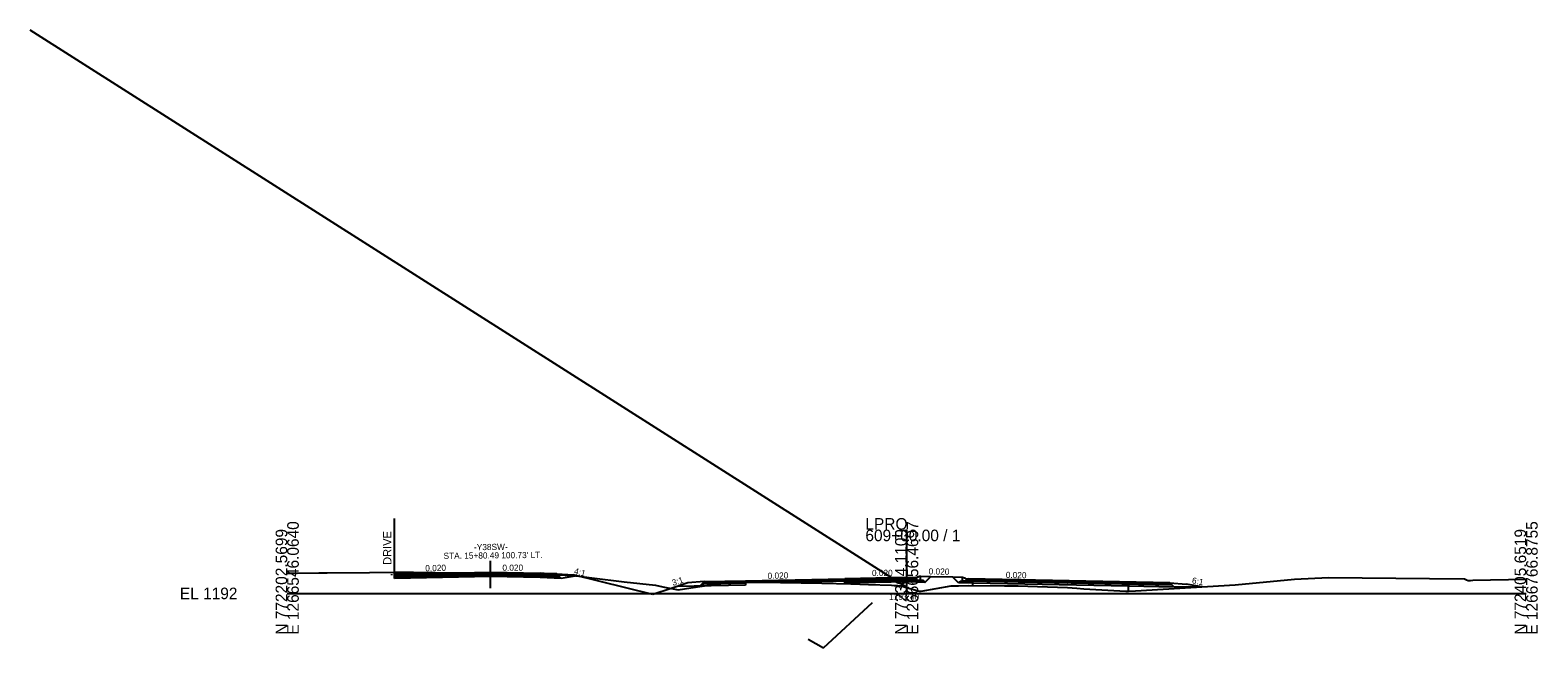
# Model space of a CAD drawing. Extents: x -3833 to 1267678, y -522 to 773248.
# Drawn here: x 1937.8 to 2302.8, y -13.2 to 136.5 of the extents above; entities that cross this region are included whole.
import ezdxf

# ---------------------------------------------------------------- set-up
doc = ezdxf.new("R2010")
doc.units = 0
for name, color, linetype in [('Exist Cross Section Cell', 7, 'Continuous'), ('Exist XS Center Line Elevation Label', 7, 'Continuous'), ('Exist XS Ground Line', 7, 'Continuous'), ('Prop CMT DNC', 7, 'Continuous'), ('Prop CMT Pvmt Course 1', 7, 'Continuous'), ('Prop CMT Pvmt Course 2', 7, 'Continuous'), ('Prop CMT Pvmt Course 3', 7, 'Continuous'), ('Prop CMT Pvmt Course 4', 7, 'Continuous'), ('Prop CMT Shld Paved Course 1', 7, 'Continuous'), ('Prop CMT Shld Paved Course 2', 7, 'Continuous'), ('Prop CMT Shld Paved Course 4', 7, 'Continuous'), ('Prop CMT Slope Fill', 7, 'Continuous'), ('Prop CMT Slope Grass', 7, 'Continuous'), ('Prop CMT Subgrade Earthwork', 7, 'Continuous'), ('Prop Conc Curb and Gutter', 7, 'Continuous'), ('Prop Conc Island Cover', 7, 'Continuous'), ('Prop Corridor Mesh Bottom', 7, 'Continuous'), ('Prop XS Ditch Slope Text', 7, 'Continuous'), ('Prop XS Finish Grade', 7, 'Continuous'), ('Prop XS SE Text', 7, 'Continuous'), ('Prop XS Shear Point Element', 7, 'Continuous'), ('Prop XS Shear Point Label', 7, 'Continuous'), ('Scratch_Level_1', 7, 'Continuous'), ('Scratch_Level_5', 7, 'Continuous'), ('Scratch_Level_9', 7, 'Continuous')]:
    doc.layers.add(name, color=color, linetype=linetype)

msp = doc.modelspace()

# ---------------------------------------------------------------- linework, layer by layer
at = {"layer": 'Exist Cross Section Cell'}
for p, q in [((2150, 0), (2150, 15.45)), ((2000, 0), (2150, 0)), ((2150, 0), (2300, 0))]:
    msp.add_line(p, q, dxfattribs=at)
at = {"layer": 'Exist XS Ground Line'}
for p, q in [((2000, 4.89), (2002.42, 4.91)), ((2002.42, 4.91), (2007.67, 4.95)), ((2007.67, 4.95), (2009.66, 4.95)), ((2009.66, 4.95), (2019.93, 5.08)), ((2019.93, 5.08), (2025.96, 5.13)), ((2025.96, 5.13), (2026.63, 5.13)), ((2026.63, 5.13), (2027.35, 5.13)), ((2027.35, 5.13), (2028.44, 5.15)), ((2028.44, 5.15), (2030.6, 5.14)), ((2030.6, 5.14), (2035.8, 5.1)), ((2035.8, 5.1), (2045.08, 5.01)), ((2045.08, 5.01), (2049.76, 4.95)), ((2049.76, 4.95), (2052.59, 4.91)), ((2052.59, 4.91), (2061.3, 4.64)), ((2061.3, 4.64), (2069.13, 4.35)), ((2069.13, 4.35), (2071.32, 4.12)), ((2071.32, 4.12), (2073.79, 3.81)), ((2073.79, 3.81), (2081.61, 2.84)), ((2243.9, 3.42), (2252.17, 3.82)), ((2252.17, 3.82), (2276.62, 3.62)), ((2081.61, 2.84), (2089.16, 1.96)), ((2089.16, 1.96), (2090.97, 1.59)), ((2090.97, 1.59), (2094.68, 0.88)), ((2094.68, 0.88), (2097.76, 1.34)), ((2097.76, 1.34), (2103.78, 2.22)), ((2103.78, 2.22), (2106.87, 2.62)), ((2106.87, 2.62), (2107.71, 2.73)), ((2107.71, 2.73), (2111.01, 2.75)), ((2111.01, 2.75), (2111.87, 2.75)), ((2111.87, 2.75), (2114.38, 2.72)), ((2114.38, 2.72), (2124.49, 2.58)), ((2124.49, 2.58), (2129.44, 2.47)), ((2129.44, 2.47), (2136.46, 2.31)), ((2136.46, 2.31), (2140.77, 2.16)), ((2140.77, 2.16), (2146.31, 1.97)), ((2146.31, 1.97), (2147.01, 1.94)), ((2147.01, 1.94), (2147.87, 1.9)), ((2147.87, 1.9), (2148.58, 1.81)), ((2148.58, 1.81), (2150.17, 1.36)), ((2150.17, 1.36), (2153.14, 0.51)), ((2153.14, 0.51), (2153.55, 0.58)), ((2153.55, 0.58), (2160.75, 1.85)), ((2160.75, 1.85), (2161.7, 1.86)), ((2161.7, 1.86), (2162.56, 1.87)), ((2162.56, 1.87), (2165.07, 1.92)), ((2165.07, 1.92), (2173.71, 1.86)), ((2173.71, 1.86), (2176.97, 1.83)), ((2176.97, 1.83), (2181.66, 1.67)), ((2181.66, 1.67), (2188.97, 1.42)), ((2188.97, 1.42), (2191.18, 1.26)), ((2191.18, 1.26), (2192.9, 1.13)), ((2192.9, 1.13), (2203.1, 0.57)), ((2203.1, 0.57), (2203.69, 0.54)), ((2203.69, 0.54), (2205.39, 0.63)), ((2205.39, 0.63), (2229.53, 2.1)), ((2229.53, 2.1), (2243.9, 3.42)), ((2276.62, 3.62), (2285.09, 3.55)), ((2285.09, 3.55), (2285.59, 3.32)), ((2285.59, 3.32), (2285.95, 3.13)), ((2285.95, 3.13), (2286.53, 3.15)), ((2286.53, 3.15), (2287.07, 3.17)), ((2287.07, 3.17), (2300, 3.46))]:
    msp.add_line(p, q, dxfattribs=at)
at = {"layer": 'Prop CMT Pvmt Course 1'}
for p, q in [((2026, 4.67), (2049.26, 5.14)), ((2049.26, 5.14), (2061.26, 4.9)), ((2061.26, 4.9), (2061.26, 4.9)), ((2061.26, 4.9), (2061.26, 4.65)), ((2061.26, 4.65), (2061.26, 4.65)), ((2061.26, 4.65), (2061.26, 4.65)), ((2111, 3.05), (2135, 3.53)), ((2111, 2.8), (2111, 3.05)), ((2111, 3.05), (2111, 3.05)), ((2135, 3.53), (2135, 3.53)), ((2135, 3.53), (2135, 3.53)), ((2135, 3.53), (2135, 3.28)), ((2135, 3.28), (2135, 3.28)), ((2213.69, 2.56), (2165, 3.53)), ((2165, 3.53), (2165, 3.53)), ((2165, 3.53), (2165, 3.53)), ((2165, 3.53), (2165, 3.28)), ((2165, 3.28), (2165, 3.28)), ((2189, 3.05), (2189, 3.05)), ((2189, 2.8), (2189, 2.8)), ((2189, 2.8), (2189, 2.8)), ((2189.06, 3.23), (2189.06, 3.23))]:
    msp.add_line(p, q, dxfattribs=at)
at = {"layer": 'Prop CMT Pvmt Course 2'}
for p, q in [((2026, 4.42), (2049.26, 4.89)), ((2049.26, 4.89), (2061.26, 4.65)), ((2061.26, 4.65), (2061.26, 4.65)), ((2061.26, 4.65), (2061.26, 4.31)), ((2061.26, 4.31), (2061.26, 4.31)), ((2061.26, 4.31), (2061.26, 4.31)), ((2150, 3.58), (2135, 3.28)), ((2135, 3.28), (2135, 3.28)), ((2135, 3.28), (2135, 2.95)), ((2135, 2.95), (2150, 3.25)), ((2135, 2.95), (2135, 2.95)), ((2151.84, 3.55), (2150, 3.58)), ((2150, 3.58), (2150, 3.58)), ((2150, 3.58), (2150, 3.58)), ((2150, 3.25), (2150, 3.25)), ((2150, 3.25), (2150, 3.25)), ((2150, 3.25), (2151.83, 3.21)), ((2165, 2.95), (2165, 3.28)), ((2165, 3.28), (2165, 3.28)), ((2165, 2.95), (2165, 2.95))]:
    msp.add_line(p, q, dxfattribs=at)
at = {"layer": 'Prop CMT Pvmt Course 3'}
msp.add_line((2154.42, 2.68), (2153.93, 3.17), dxfattribs=at)
at = {"layer": 'Prop CMT Pvmt Course 4'}
for p, q in [((2026, 4.09), (2049.26, 4.55)), ((2049.26, 4.55), (2061.26, 4.31)), ((2061.26, 4.31), (2061.26, 4.31)), ((2061.26, 4.31), (2061.26, 3.85)), ((2061.26, 3.85), (2061.26, 3.85)), ((2061.26, 3.85), (2061.26, 3.85)), ((2135, 2.34), (2135, 2.95)), ((2135, 2.95), (2135, 2.95)), ((2135, 2.95), (2135, 2.95)), ((2150, 3.25), (2150, 3.25)), ((2150, 3.25), (2150, 3.25)), ((2153.34, 3.19), (2153.93, 3.17)), ((2162.54, 2.54), (2162.99, 2.99)), ((2162.99, 2.99), (2163.49, 2.98)), ((2165, 2.95), (2165, 2.95)), ((2165, 2.95), (2165, 2.95)), ((2166, 2.47), (2166, 3.51)), ((2203.69, 1.72), (2166, 2.47)), ((2203.69, 2.76), (2203.69, 1.72))]:
    msp.add_line(p, q, dxfattribs=at)
at = {"layer": 'Prop CMT Shld Paved Course 1'}
for p, q in [((2062.24, 4.85), (2061.26, 4.9)), ((2061.26, 4.65), (2061.26, 4.65)), ((2061.26, 4.65), (2062.48, 4.59)), ((2065.26, 4.72), (2062.24, 4.85)), ((2062.48, 4.59), (2062.54, 4.59)), ((2062.54, 4.59), (2065.53, 4.45)), ((2065.53, 4.45), (2065.26, 4.72)), ((2150, 3.83), (2135, 3.53)), ((2151.85, 3.79), (2150, 3.83)), ((2150, 3.83), (2150, 3.83)), ((2150, 3.83), (2150, 3.83)), ((2100.74, 2.6), (2101, 2.85)), ((2111, 2.8), (2100.74, 2.6)), ((2101, 2.85), (2111, 3.05)), ((2111, 3.05), (2111, 2.8)), ((2135, 3.53), (2135, 3.53)), ((2135, 3.53), (2135, 3.28)), ((2150, 3.58), (2150, 3.58)), ((2150, 3.58), (2150, 3.58)), ((2165, 3.53), (2165, 3.53)), ((2213.95, 2.3), (2213.69, 2.56))]:
    msp.add_line(p, q, dxfattribs=at)
at = {"layer": 'Prop CMT Shld Paved Course 2'}
for p, q in [((2062.48, 4.59), (2061.26, 4.65)), ((2061.26, 4.31), (2061.26, 4.31)), ((2061.26, 4.31), (2062.7, 4.25)), ((2065.53, 4.45), (2062.48, 4.59)), ((2062.7, 4.25), (2062.88, 4.24)), ((2062.88, 4.24), (2065.88, 4.11)), ((2065.88, 4.11), (2065.53, 4.45)), ((2100.41, 2.26), (2100.74, 2.6)), ((2111, 2.47), (2100.41, 2.26)), ((2111, 2.75), (2111, 2.8)), ((2111, 2.8), (2111, 2.8)), ((2111, 2.8), (2111.01, 2.8)), ((2111.01, 2.75), (2111, 2.75)), ((2111.01, 2.8), (2111.87, 2.82)), ((2111.87, 2.75), (2111.01, 2.75)), ((2111.87, 2.82), (2114.38, 2.87)), ((2111.87, 2.82), (2111.87, 2.82)), ((2114.38, 2.72), (2111.87, 2.75)), ((2111.87, 2.75), (2111.87, 2.75)), ((2114.38, 2.87), (2124.49, 3.07)), ((2114.38, 2.87), (2114.38, 2.87)), ((2119.78, 2.64), (2114.38, 2.72)), ((2114.38, 2.72), (2114.38, 2.72)), ((2124.49, 2.74), (2119.78, 2.64)), ((2119.78, 2.64), (2119.78, 2.64)), ((2119.78, 2.64), (2119.78, 2.64)), ((2124.49, 3.07), (2129.44, 3.17)), ((2124.49, 3.07), (2124.49, 3.07)), ((2129.44, 2.84), (2124.49, 2.74)), ((2129.44, 3.17), (2135, 3.28)), ((2129.44, 3.17), (2129.44, 3.17)), ((2135, 2.95), (2129.44, 2.84)), ((2129.44, 2.84), (2129.44, 2.84)), ((2135, 3.28), (2135, 3.28)), ((2135, 3.28), (2135, 3.28)), ((2135, 3.28), (2135, 2.95)), ((2135, 2.95), (2135, 2.95)), ((2165, 3.28), (2165, 3.28)), ((2165, 3.28), (2165, 3.28)), ((2165, 3.28), (2165.07, 3.28)), ((2165.07, 2.95), (2165, 2.95)), ((2165, 2.95), (2165, 2.95)), ((2165.07, 3.28), (2165.07, 3.28)), ((2165.07, 3.28), (2173.71, 3.11)), ((2173.71, 2.77), (2165.07, 2.95)), ((2165.07, 2.95), (2165.07, 2.95)), ((2173.71, 3.11), (2173.71, 3.11)), ((2173.71, 3.11), (2176.97, 3.04)), ((2176.97, 2.71), (2173.71, 2.77)), ((2173.71, 2.77), (2173.71, 2.77)), ((2176.97, 3.04), (2181.66, 2.95)), ((2181.66, 2.62), (2176.97, 2.71)), ((2181.66, 2.95), (2181.66, 2.95)), ((2181.66, 2.95), (2213.95, 2.3)), ((2214.29, 1.96), (2181.66, 2.62)), ((2181.66, 2.62), (2181.66, 2.62)), ((2188.97, 2.8), (2188.97, 2.8)), ((2188.97, 2.8), (2189, 2.8)), ((2189, 2.47), (2188.97, 2.47)), ((2188.97, 2.47), (2188.97, 2.47)), ((2189, 2.8), (2189, 2.8)), ((2214.28, 1.97), (2213.95, 2.3))]:
    msp.add_line(p, q, dxfattribs=at)
at = {"layer": 'Prop CMT Shld Paved Course 4'}
for p, q in [((2061.26, 3.85), (2061.26, 3.85)), ((2066.36, 3.62), (2065.88, 4.11)), ((2099.94, 1.79), (2100.41, 2.26)), ((2100.41, 2.26), (2100.91, 2.27)), ((2214.75, 1.5), (2214.28, 1.97))]:
    msp.add_line(p, q, dxfattribs=at)
at = {"layer": 'Prop CMT Slope Grass'}
for p, q in [((2065.26, 4.72), (2069.26, 4.54)), ((2153.37, 4.17), (2155.86, 4.12)), ((2161.07, 4.01), (2163.49, 3.96)), ((2101, 2.85), (2097, 2.53)), ((2213.69, 2.56), (2217.69, 2.24)), ((2221.46, 1.61), (2217.69, 2.24))]:
    msp.add_line(p, q, dxfattribs=at)
at = {"layer": 'Prop CMT Subgrade Earthwork'}
for p, q in [((2026, 3.63), (2026, 5.13)), ((2049.26, 4.09), (2026, 3.63)), ((2061.26, 3.85), (2049.26, 4.09)), ((2066.36, 3.62), (2061.26, 3.85)), ((2070.19, 4.24), (2066.36, 3.62)), ((2154.42, 2.68), (2155.86, 4.12)), ((2162.54, 2.54), (2161.07, 4.01)), ((2111, 2.01), (2094.45, 1.68)), ((2111, 2.75), (2111, 2.01)), ((2149.99, 2.79), (2135, 2.49)), ((2135, 2.34), (2135, 2.49)), ((2154.42, 2.68), (2149.99, 2.79)), ((2166, 2.47), (2162.54, 2.54)), ((2166, 1.91), (2166, 2.47)), ((2203.69, 0.54), (2203.69, 1.72)), ((2214.76, 1.5), (2203.69, 1.72)), ((2221.46, 1.61), (2214.76, 1.5))]:
    msp.add_line(p, q, dxfattribs=at)
at = {"layer": 'Prop Conc Curb and Gutter'}
for p, q in [((2151.85, 3.79), (2151.83, 3.21)), ((2151.85, 3.79), (2151.85, 3.79)), ((2151.88, 3.79), (2151.85, 3.79)), ((2152.6, 3.78), (2151.88, 3.79)), ((2152.61, 3.95), (2152.6, 3.95)), ((2152.6, 3.95), (2152.6, 3.78)), ((2152.6, 3.78), (2152.6, 3.78)), ((2153.37, 4.17), (2152.61, 3.95)), ((2153.34, 3.19), (2153.37, 4.17)), ((2163.49, 2.98), (2163.49, 3.96)), ((2163.49, 3.96), (2163.49, 3.96)), ((2163.49, 3.96), (2163.49, 3.96)), ((2163.49, 3.96), (2164.25, 3.71)), ((2164.25, 3.71), (2164.25, 3.71)), ((2164.25, 3.71), (2164.25, 3.55)), ((2151.83, 3.21), (2153.34, 3.19)), ((2165, 2.95), (2163.49, 2.98)), ((2163.49, 2.98), (2163.49, 2.98)), ((2164.25, 3.55), (2165, 3.53)), ((2164.25, 3.55), (2164.25, 3.55)), ((2165, 3.53), (2165, 3.53)), ((2165, 3.53), (2165, 2.95))]:
    msp.add_line(p, q, dxfattribs=at)
at = {"layer": 'Prop Conc Island Cover'}
for p, q in [((2163.49, 3.96), (2163.49, 3.96)), ((2163.49, 3.71), (2163.49, 3.71))]:
    msp.add_line(p, q, dxfattribs=at)
at = {"layer": 'Prop Corridor Mesh Bottom'}
for p, q in [((2061.26, 4.9), (2061.26, 4.65)), ((2111, 3.05), (2111, 2.8)), ((2135, 3.53), (2135, 3.28)), ((2165, 3.53), (2165, 3.28))]:
    msp.add_line(p, q, dxfattribs=at)
at = {"layer": 'Prop XS Finish Grade'}
for p, q in [((2088.51, -0.3), (2069.26, 4.54)), ((2155.86, 4.12), (2161.07, 4.01)), ((2163.49, 3.96), (2163.49, 3.96)), ((2093.01, 1.2), (2088.51, -0.3)), ((2097, 2.53), (2093.01, 1.2))]:
    msp.add_line(p, q, dxfattribs=at)
at = {"layer": 'Prop XS Shear Point Element'}
for p, q in [((2026, 5.12), (2026, 18.11)), ((2049.26, 1.31), (2049.26, 7.88))]:
    msp.add_line(p, q, dxfattribs=at)
at = {"layer": 'Scratch_Level_1'}
msp.add_line((2150, 1.4), (1937.75, 136.46), dxfattribs=at)
at = {"layer": 'Scratch_Level_5'}
for p, q in [((2129.9, -13.19), (2141.75, -2.17)), ((2126.11, -11.09), (2129.9, -13.19))]:
    msp.add_line(p, q, dxfattribs=at)
at = {"layer": 'Scratch_Level_9'}
for points in [[(2025.26, 4.67), (2025.26, 4.42)], [(2025.26, 4.66), (2025.26, 4.41)]]:
    msp.add_lwpolyline(points, dxfattribs=at)

# ---------------------------------------------------------------- texts
at = {"layer": 'Exist Cross Section Cell'}
for s, p in [('LPRO', (2140, 15.45)), ('609+00.00 / 1', (2140, 12.65)), ('EL 1192', (1974, -1.4))]:
    msp.add_text(s, height=2.8, dxfattribs=at).set_placement(p)
for s, p in [('N 772202.5699', (2000, -10)), ('E 1266546.0640', (2002.8, -10)), ('N 772304.1109', (2150, -10)), ('E 1266656.4697', (2152.8, -10)), ('N 772405.6519', (2300, -10)), ('E 1266766.8755', (2302.8, -10))]:
    msp.add_text(s, height=2.8, rotation=90, dxfattribs=at).set_placement(p)
at = {"layer": 'Exist XS Center Line Elevation Label'}
msp.add_text('1193.40', height=1.5, dxfattribs=at).set_placement((2145.76, -1.56))
at = {"layer": 'Prop CMT DNC'}
msp.add_text('X', height=0.00025, rotation=358.0725, dxfattribs=at).set_placement((2152.6, 3.78))
for p in [(2111, 3.05), (2111, 3.05), (2135, 3.53), (2135, 3.53), (2164.25, 3.55), (2165, 3.53), (2165, 3.53), (2189, 3.05)]:
    msp.add_text('X', height=0.00025, dxfattribs=at).set_placement(p)
at = {"layer": 'Prop CMT Slope Fill'}
for p in [(2023.26, 4.54), (2049.26, 5.14), (2061.26, 4.9)]:
    msp.add_text('X', height=0.00025, dxfattribs=at).set_placement(p)
at = {"layer": 'Prop XS Ditch Slope Text'}
for s, rotation, p in [('4:1', 345.2605, (2069.33, 4.77)), ('3:1', 18.0377, (2093.43, 1.79)), ('6:1', 349.1424, (2218.99, 2.46))]:
    msp.add_text(s, height=1.5, rotation=rotation, dxfattribs=at).set_placement(p)
at = {"layer": 'Prop XS SE Text'}
for s, rotation, p in [('-Y38SW-', 0.5826, (2045.24, 10.46)), ("STA. 15+80.49 100.73' LT.", 0.5826, (2037.86, 8.35)), ('0.020', 1.397, (2033.45, 5.35)), ('0.020', 0.2693, (2052.11, 5.47)), ('0.020', 1.397, (2116.34, 3.51)), ('0.020', 0.2693, (2141.6, 4.2)), ('0.020', 358.8542, (2155.31, 4.61)), ('0.020', 358.8542, (2173.99, 3.74))]:
    msp.add_text(s, height=1.5, rotation=rotation, dxfattribs=at).set_placement(p)
at = {"layer": 'Prop XS Shear Point Label'}
msp.add_text('DRIVE', height=2, rotation=90, dxfattribs=at).set_placement((2025.23, 6.92))

doc.saveas('drawing.dxf')
